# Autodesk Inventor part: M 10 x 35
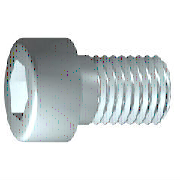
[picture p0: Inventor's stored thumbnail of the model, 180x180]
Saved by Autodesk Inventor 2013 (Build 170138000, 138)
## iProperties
IsCustomPart: 0
Created: 2009-02
Part Number: M 10 x 35
Material: 강, 연강
Description: 6각머리 태핑 나사
Document SubType Name: Modeling
Standard: KS B 1003
Designer: KYOUNG IL JANG
Standards Organization: KS
Language: ko-KR
Size Designation: M 10 x 35
Categories: <MemberInstance><Categories><Category DisplayName="조임쇠" InternalName="e4da775c-781d-43d5-af7c-5136215cf5a6" Mnemonic="FSTN"><Category DisplayName="볼트" InternalN
Density: 1 g/cm^3
Author: KYOUNG IL JANG
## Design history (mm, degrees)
sketch "스케치1"
  geometry: L1 (-2.333, 0)-(35, 0); L2 (35, 0)-(35, 5); L3 (35, 5)-(3.75, 5); L4 (3.75, 5)-(2.83, 5); L5 (2.83, 5)-(0, 5); L6 (0, 5)-(0, 8); L7 (0, 8)-(-10, 8); L8 (-10, 8)-(-10, 4.619); L9 (-10, 4.619)-(-5, 4.619); L10 (-5, 4.619)-(-2.333, 0); L11 (-19, 0)-(44, 0) reference; L12 (0, -1.6)-(0, 9.6) reference; L13 (3.75, 5)-(0, 5)
  constraints: 22 end point, 6 parallel, 2 collinear, 2 perpendicular, 1 horizontal, 1 point on line
  dimensions: "d1" = 31.25 distance from line of L3.end L2 (= GEL); "d2" = 0.92028 distance of L4.end L3.end (computed from GAL); "d3" = 10 distance between parallel lines of L8 L6 (= KOH); "d4" = 5 distance of L8.end L9.end (= INTI); "d5" = 60 deg angle of L10 L1; "d6" = 10 diameter of L3 L1 (= GD); "d7" = 10 diameter of L5 L1 (= BDM); "d8" = 9.2376 diameter of L9 L1 (= 1.1547 x SW); "d9" = 16 diameter of L7 L1 (= KOD); "d26" = 35 distance between parallel lines of L12 L2 (= NLG)
revolve "본체" sketch "스케치1" stored, may be unused: angle "d10" = 90 deg
sketch "스케치2"
  geometry: L1 (0, -11.2)-(0, 11.2) reference; L2 (-11.2, 0)-(11.2, 0) reference; L3 (4.619, 0)-(2.309, -4); L4 (2.309, -4)-(-2.309, -4); L5 (-2.309, -4)-(-4.619, 0); L6 (-4.619, 0)-(-2.309, 4); L7 (-2.309, 4)-(2.309, 4); L8 (2.309, 4)-(4.619, 0); 2 further points
  constraints: 12 end point, 1 coincident, 1 horizontal alignment, 1 point on line, 12 other
extrude "슬롯" join sketch "스케치2" stored distance "d11" = 10; taper "d12" = 0 deg
workplane "Work Plane1"
fillet "Fillet2" dims "d30" = 0.1 (= R)
body "Solid1"
fillet "모깎기1" dims "d17" = 1 (= RR)
feature "스레드" dims "d13" = 31.25 (= GEL), "d14" = 0
chamfer "모따기1" distance "d15" = 0.92018 (= -0.5 x SPD + 0.5 x GD); stored, may be unused: second distance "d16" = 0.92018 (= GUL), angle "d27" = 45 deg
other parameters: "GD" = 10 (= NND) [user parameter; used in 2 equation terms], "NLG" = 35 [user parameter; used in 1 equation term], "GEL" = 31.25 [user parameter; used in 2 equation terms], "KOD" = 16 [user parameter; used in 1 equation term], "KOH" = 10 [user parameter; used in 1 equation term], "INTI" = 5 [user parameter; used in 1 equation term], "GAL" = 0.92018 (= 0.61345 x PTC) [user parameter; used in 1 equation term], "GUL" = 0.92018 (= 0.61345 x PTC) [user parameter; used in 1 equation term], "BDM" = 10 (= NND) [user parameter; used in 1 equation term], "SW" = 8 [user parameter; used in 2 equation terms], "RR" = 1 [user parameter; used in 1 equation term], "SPD" = 8.15965 (= NND - 1.2269 x PTC) [user parameter; used in 1 equation term], "d19" = 0, "d28" = 0, "d29" = 0, "R" = 0.1 [user parameter; used in 1 equation term], "PHH" = 0.4 [user parameter], "GD1" = 8.15965 (= THREADDIA - 1.2269 x PTC) [user parameter], "FAWI" = 45 deg [user parameter], "TPU" = 6.66667 (computed from PTC) [user parameter], "PTC" = 1.5 [user parameter; used in 5 equation terms], "TOA" = 30 deg [user parameter], "E0" = 9.24 (= 1.155 x SW) [user parameter]
